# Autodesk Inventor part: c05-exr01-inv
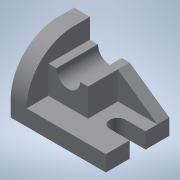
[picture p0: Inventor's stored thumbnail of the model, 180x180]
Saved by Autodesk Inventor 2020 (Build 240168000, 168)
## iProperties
Created: 2001-11
Part Number: c05-exr01-inv
Document SubType Name: Modeling
Designer: Renu Muthoo
Density: 1 g/cm^3
Material: Generic
Appearance: Default
Control State: 0
Master: False
Checked Out: False
Shininess: 77.0
Length Units: 11269
Angle Units: 11279
Time Units: 11290
Mass Units: 11283
Length Display Precision: 3
Angle Display Precision: 2
Density: 0.0
Volumn: 0.0
Area: 0.0
PropertySet Name: Model Information
Author: Renu Muthoo
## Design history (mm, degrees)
sketch "Sketch1"
  geometry: L1 (-76, 32)-(20, 32); L2 (20, -32)-(-76, -32); L3 (-76, -32)-(-76, 32); L4 (20, 8)-(0, 8); L5 (0, -8)-(20, -8); L6 (20, 32)-(20, 8); L7 (20, -8)-(20, -32); A1 r 8 centre (0, 0) between (0, 8) and (0, -8); 1 further point
  constraints: 14 end point, 4 parallel, 3 perpendicular, 2 point on circle, 2 tangent, 1 centre point, 1 coincident, 1 collinear, 1 horizontal, 1 other
  dimensions: "d18" = 96 distance between parallel lines of L3 L7; "d19" = 20 distance from line of L7 point (0, 0); "d20" = 32 distance from line of point (0, 0) L2; "d21" = 64 distance between parallel lines of L2 L1; "d22" = 8 radius of A1
extrude "Extrusion1" new body sketch "Sketch1" distance "d5" = 16; taper "d6" = 0 deg
sketch "Sketch2"
  geometry: L1 (16, 64)-(64, 64); L2 (64, 64)-(64, 48); L3 (16, 0)-(16, 0); L4 (16, 0)-(16, 64); L5 (0, 64)-(16, 64) reference; L6 (16, 0)-(16, 64) reference; L7 (0, 0)-(16, 0) reference; L8 (0, 0)-(0, 64) reference; A1 r 48 centre (16, 48) between (16, 0) and (64, 48)
  constraints: 8 end point, 3 collinear, 3 perpendicular, 2 point on circle, 2 tangent, 1 centre point, 1 horizontal
  dimensions: "d7" = 64 distance between parallel lines of L2 L8; "d8" = 48 radius of A1
extrude "Extrusion2" join sketch "Sketch2" distance "d9" = 16; taper "d10" = 0 deg
sketch "Sketch3"
  geometry: L1 (16, -44)-(16, -16); L2 (16, -16)-(56, -16); L3 (56, -16)-(56, -44); L4 (56, -44)-(48, -44); L5 (24, -44)-(16, -44); L6 (16, -64)-(16, -16) reference; L7 (16, -16)-(96, -16) reference; A1 r 12 centre (36, -44) between (48, -44) and (24, -44)
  constraints: 10 end point, 3 collinear, 3 parallel, 2 equal length, 2 point on circle, 1 centre point, 1 perpendicular, 1 point on line, 1 vertical
  dimensions: "d11" = 28 distance of L2.end L3.end; "d23" = 12 radius of A1; "d24" = 20 distance from line of A1.centre L6
extrude "Extrusion3" join sketch "Sketch3" distance "d14" = 42; taper "d15" = 0 deg
sketch "Sketch4"
  geometry: L1 (56, -16)-(96, -16) reference; L2 (56, -16)-(56, -44) reference; L3 (96, -16)-(56, -44)
  constraints: 2 end point
extrude "Extrusion4" join sketch "Sketch4" distance "d16" = 12; taper "d17" = 0 deg
body "Solid1"
